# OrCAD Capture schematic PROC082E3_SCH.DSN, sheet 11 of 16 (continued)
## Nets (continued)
VREG_3V3: C335.1 C354.1 C355.1 C357.1 C358.1 C360.1 C361.1 C485.1 C491.1 C492.1 C493.1 C507.1 C511.1 C512.1 C514.1 C515.1 C517.1 C518.1 L25.2 R199.1 R245.2 TP55.1(TP) U29.1(IN1) U29.2(IN2) U29.4(BIAS) U30.1(IN1) U30.2(IN2) U30.4(BIAS) U31.1(IN1) U31.2(IN2) U31.4(BIAS) U33.1(VIN1) U33.2(VIN2) U33.16(VIN3)
VREG_3V3_CBOOT: C338.1 U28.13(BOOT)
VREG_3V3_COMP: C345.1 R196.1 U28.8(COMP)
VREG_3V3_EN: R253.2 R254.1 U28.10(EN)
VREG_3V3_FB: R198.1 R199.2 U28.7(VSENSE)
VREG_3V3_PG: TP32.1(TP) U28.14(PWRGD)
VREG_3V3_RT/CLK: R193.1 U28.1(RT/CLK)
VREG_3V3_SS/TR: C350.1 U28.9(SS/TR)
VREG_3V3_SW: C338.2 L25.1 U28.11(PH1) U28.12(PH2)
N24518728: C348.1 R196.2
N24522043: C501.1 R244.2
N24608149: D1.2 F2.2 TP37.1(TP)
N24763505: U35.6(PGATE) U36.4(GATE)
N24763516: D3.3(K) L30.1 U36.1(S1) U36.2(S2) U36.3(S3)
N24766225: R257.2 U35.2(RT)
N24772813: C523.2 R256.1 U35.1(ADJ)
N24774750: C522.1 U35.7(VCC)

Not connected (* = marked no-connect by the designer): D1 1*; U19 2(PG)*

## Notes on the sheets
sheet 11
- 12V / 20V Input from CSI Connector
- POWER
- DC-DC 3.3V to 1.8V
- Iout 3A
  Vout 1.8V
- Phoenix Contact
  12Amp
- 3.3V_REG to 1.1V HUB1
- Iout 1.5A
  Vout 1.1V
- Iout: 10A
  Vout: 11.3V
- Iout 5A
  Vout 3.3V
- DC-DC STAGE-1
  12V to 3.3V_REG
- 3.3V_REG to 1.1V HUB2
- Iout 1.5A
  Vout 1.1V
- DC-DC STAGE-2
  3.3V_REG to 1.1V
- 3.3V_REG to 1.1V HUB3
- Iout 5A
  Vout 1.1V
- Iout 1.5A
  Vout 1.1V
